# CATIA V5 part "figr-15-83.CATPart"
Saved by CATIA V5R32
Part number: Part1
Bounding box of the stored display mesh (mm): x 0 to 27, y -46 to 46, z -30 to 30
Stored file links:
  D:\PROJECTS\Project 2022\CATIA V5 6R 2022\Resources\Part Files\c15_catia_v5_6r2022_prt\figr-15-83.CATPart
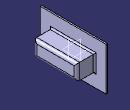
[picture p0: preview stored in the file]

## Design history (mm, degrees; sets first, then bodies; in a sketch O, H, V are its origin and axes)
SheetMetalParameters1: Thickness 2, BendRadius 4, KFactor 0.400515 {= log(min(100,max(20*SheetMetalParameters1.BendRadius,SheetMetalParameters1.Thickness)/SheetMetalParameters1.Thickness))/log(100)/2}, ReliefRadialLength 1, ReliefAxialLength 2, MinimumBendRadius 0
Body1 (main body)
  Sketch1 on yz-plane, origin (0, 0, 0), H (0, 1, 0), V (0, 0, 1)
    line L1 (46, 30) -> (46, -30)
    line L2 (46, -30) -> (-46, -30)
    line L3 (-46, -30) -> (-46, 30)
    line L4 (-46, 30) -> (46, 30)
    vertical: L1 V, L3 V
    horizontal: L2 H, L4 H
    equidistance: L1 L3 O, L2 L4 O
  Wall1: Thickness 2, Profile Sketch1, OffsetValue 0
  Sketch2 on face of Wall1, origin (2, 0, 0), H (0, 1, 0), V (0, 0, 1)
    line L1 (28, 9) -> (28, -9)
    line L2 (28, -9) -> (-28, -9)
    line L3 (-28, -9) -> (-28, 9)
    line L4 (-28, 9) -> (28, 9)
    vertical: L1 V, L3 V
    horizontal: L2 H, L4 H
    equidistance: L1 L3 O, L2 L4 O
  d_Stamp1: NewRoot_AttribNormalisation "No Standard", Stamp_FilletRadius 2, Stamp_IntersectFilletRadius 2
